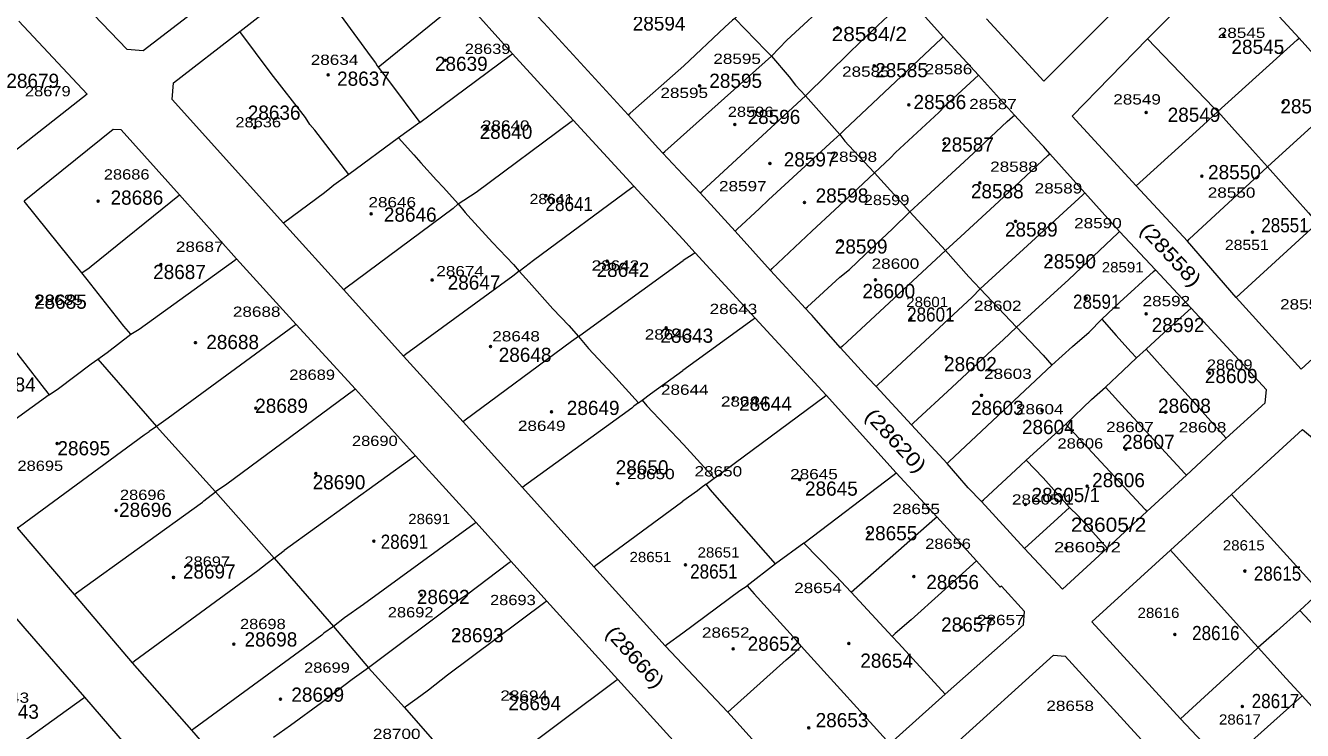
# Model space of a CAD drawing. Extents: x 650553 to 652508, y 239277 to 241647.
# Drawn here: x 651208.2 to 651532.3, y 240545.4 to 240724.2 of the extents above; entities that cross this region are included whole.
import ezdxf

# ---------------------------------------------------------------- set-up
doc = ezdxf.new("R2010")
doc.units = 0
doc.header["$PDMODE"] = 32
doc.header["$PDSIZE"] = 0.5
for name, color, linetype in [('19', 7, 'Continuous'), ('20', 7, 'Continuous'), ('6', 7, 'Continuous')]:
    doc.layers.add(name, color=color, linetype=linetype)
doc.layers.add('3', color=7, linetype='Continuous', lineweight=13)
doc.layers.add('5', color=7, linetype='Continuous', lineweight=13)

msp = doc.modelspace()

# ---------------------------------------------------------------- linework, layer by layer
at = {"layer": '3'}
for p, q in [((651450.066, 240711.621), (651459.242, 240701.47)), ((651375, 240686.46), (651369.97, 240691.81)), ((651498.782, 240591.135), (651514.288, 240605.241)), ((651461.794, 240591.569), (651450.843, 240603.463)), ((651427.585, 240542.041), (651441.626, 240554.652))]:
    msp.add_line(p, q, dxfattribs=at)
for points in [[(651262.55, 240722.73), (651280.74, 240736.96), (651297.28, 240750)], [(651302.75, 240750), (651319.13, 240731.15), (651331.81, 240717.05), (651347.16, 240700.26), (651362.6, 240683.5), (651375, 240670.03)], [(651369.97, 240691.81), (651368.88, 240693.01), (651361.16, 240701.58), (651339.76, 240724.88), (651328.09, 240737.32), (651316.83, 240750)], [(651255.48, 240731.26), (651238.03, 240717.81), (651233.93, 240718.13), (651208.28, 240744.9)], [(651492.971, 240720.815), (651513.155, 240740.984), (651531.466, 240721.038), (651544.042, 240707.095)], [(651450.066, 240711.621), (651441.147, 240721.392), (651432.124, 240731.442)], [(651452.07, 240725.954), (651466.7, 240710.154), (651486.051, 240729.467)], [(651206.48, 240725.3), (651223.8, 240706.84), (651205.18, 240692.18), (651190.09, 240680.31), (651175.31, 240668.77)], [(651273.67, 240674.07), (651245.34, 240705.49), (651245.71, 240709.71), (651262.55, 240722.73)], [(651490.103, 240683.542), (651473.849, 240701.275), (651492.971, 240720.815)], [(651459.242, 240701.47), (651466.169, 240693.962), (651466.625, 240693.468)], [(651247.26, 240681.25), (651232.45, 240697.8), (651230.43, 240697.87), (651207.83, 240679.65)], [(651468.174, 240691.712), (651467.071, 240692.962), (651466.625, 240693.468)], [(651504.03, 240652.528), (651494.997, 240662.26), (651485.912, 240672.017), (651477.107, 240681.763), (651468.174, 240691.712)], [(651375, 240686.46), (651379.385, 240681.794), (651388.317, 240672.1), (651397.237, 240662.126), (651406.195, 240652.406)], [(651515.523, 240655.238), (651503.098, 240669.537), (651490.103, 240683.542)], [(651375, 240540.13), (651358.51, 240558.37), (651340.48, 240578.22), (651331.44, 240588.29), (651322.55, 240598.18), (651307.18, 240615.11), (651291.88, 240631.98), (651276.83, 240648.43), (651261.75, 240665.07), (651247.26, 240681.25)], [(651386.452, 240550.075), (651370.54, 240566.91), (651352.46, 240586.94), (651334.34, 240607.07), (651319.27, 240623.71), (651304.14, 240640.39), (651288.94, 240657.22), (651273.67, 240674.07)], [(651375, 240670.03), (651378.161, 240666.59), (651393.367, 240650.006), (651411.384, 240630.427), (651429.147, 240610.758), (651439.535, 240599.585)], [(651552.783, 240656.051), (651531.957, 240637.06), (651515.523, 240655.238)], [(651406.195, 240652.406), (651407.346, 240651.167), (651407.834, 240650.642)], [(651415.077, 240642.469), (651408.255, 240650.167), (651407.834, 240650.642)], [(651512.913, 240619.579), (651522.834, 240628.544), (651523.235, 240631.812), (651504.03, 240652.528)], [(651424.073, 240632.686), (651422.042, 240634.784), (651415.077, 240642.469)], [(651450.843, 240603.463), (651447.471, 240606.976), (651444.838, 240609.985), (651442.127, 240613.146), (651433.055, 240622.967), (651424.073, 240632.686)], [(651295.65, 240493.45), (651290, 240500), (651285.79, 240504.89), (651259.52, 240534.92), (651250.39, 240545.47), (651235.33, 240562.59), (651220.57, 240579.93), (651206.08, 240596.78), (651191.08, 240613.86), (651178.77, 240628.25)], [(651514.288, 240605.241), (651532.372, 240621.712), (651558.3, 240600.133)], [(651273.44, 240495.96), (651269.97, 240500), (651254.58, 240517.89), (651246.43, 240527.23), (651238.05, 240536.69), (651223.17, 240553.84), (651208.09, 240571.29), (651193.7, 240587.9), (651178.92, 240605.09), (651167.95, 240618.06)], [(651482.725, 240591.652), (651492.847, 240600.974), (651502.894, 240610.13), (651512.913, 240619.579)], [(651439.535, 240599.585), (651442.973, 240595.755), (651446.245, 240592.076), (651449.555, 240588.435)], [(651558.3, 240600.133), (651576.968, 240584.586), (651595.445, 240569.14), (651576.219, 240550.158), (651565.481, 240539.702), (651554.984, 240529.272), (651535.929, 240510.959), (651512.56, 240536.549), (651501.394, 240548.39)], [(651461.794, 240591.569), (651471.364, 240581.255), (651482.725, 240591.652)], [(651441.626, 240554.652), (651461.507, 240572.227), (651461.755, 240575.583), (651455.903, 240582.029), (651455.612, 240581.723), (651449.555, 240588.435)], [(651501.394, 240548.39), (651478.878, 240572.937), (651498.782, 240591.135)], [(651443.339, 240541.167), (651469.158, 240564.482), (651472.119, 240564.219), (651489.626, 240545.044), (651506.288, 240526.995)], [(651386.452, 240550.075), (651408.664, 240525.362), (651427.585, 240542.041)]]:
    msp.add_lwpolyline(points, dxfattribs=at)
at = {"layer": '5'}
for p, q in [((651494.997, 240718.782), (651492.971, 240720.815)), ((651297.02, 240714.77), (651297.44, 240714.04)), ((651297.44, 240714.04), (651297.71, 240713.68)), ((651414.853, 240696.6), (651415.965, 240697.649)), ((651423.671, 240686.842), (651432.655, 240676.931)), ((651222.41, 240661.46), (651207.83, 240679.65)), ((651317.97, 240678.97), (651316.71, 240677.8)), ((651432.655, 240676.931), (651441.701, 240667.136)), ((651349.8, 240646.28), (651375.111, 240664.641)), ((651223.8, 240659.77), (651222.41, 240661.46)), ((651333.45, 240661.88), (651331.88, 240660.68)), ((651234.88, 240645.93), (651236.98, 240647.19)), ((651348.52, 240645.36), (651346.75, 240644.1)), ((651348.52, 240645.36), (651349.8, 240646.28)), ((651241.42, 240622.49), (651239.53, 240621.26)), ((651462.204, 240613.935), (651472.263, 240623.105)), ((651382.936, 240609.372), (651375.204, 240617.968)), ((651259.27, 240607.88), (651256.38, 240605.9)), ((651398.577, 240587.644), (651383.137, 240605.218)), ((651271.23, 240589.14), (651273.77, 240591.03)), ((651318.53, 240578.69), (651295.23, 240561.28)), ((651320.06, 240579.76), (651318.53, 240578.69)), ((651428.145, 240569.276), (651417.757, 240580.474)), ((651405.068, 240566.804), (651406.666, 240564.996)), ((651441.626, 240554.652), (651429.755, 240567.557)), ((651386.452, 240550.075), (651401.239, 240563.287)), ((651427.585, 240542.041), (651406.666, 240564.996))]:
    msp.add_line(p, q, dxfattribs=at)
for points in [[(651397.508, 240716.45), (651396.065, 240717.916), (651388.221, 240726.041), (651389.808, 240727.583), (651392.535, 240729.948), (651401.538, 240738.647), (651413.8, 240750)], [(651280.74, 240736.96), (651281.106, 240736.46), (651295.91, 240716.23), (651297.02, 240714.77)], [(651397.508, 240716.45), (651401.448, 240720.514), (651413.187, 240731.421), (651416.952, 240735.001)], [(651297.71, 240713.68), (651318.63, 240730.742), (651319.13, 240731.15)], [(651406.137, 240706.385), (651417.43, 240717.455), (651422.004, 240721.904), (651432.124, 240731.442)], [(651388.221, 240726.041), (651387.627, 240725.567), (651385.693, 240723.853), (651375.231, 240713.996)], [(651308.23, 240699.65), (651302.85, 240695.7), (651290.19, 240686.46), (651281.63, 240697.69), (651280.36, 240699.12), (651279.24, 240700.86), (651270.51, 240712.06), (651262.55, 240722.73)], [(651415.965, 240697.649), (651440.647, 240720.921), (651441.147, 240721.392)], [(651510.816, 240702.43), (651530.966, 240720.587), (651531.466, 240721.038)], [(651494.997, 240718.782), (651509.769, 240703.453), (651510.816, 240702.43), (651507.101, 240698.952), (651490.103, 240683.542)], [(651308.23, 240699.65), (651331.31, 240716.681), (651331.81, 240717.05)], [(651369.97, 240691.81), (651370.47, 240692.257), (651397.508, 240716.45)], [(651397.508, 240716.45), (651402.046, 240711.216), (651403.645, 240709.141), (651406.137, 240706.385)], [(651297.71, 240713.68), (651300.57, 240709.91), (651308.23, 240699.65)], [(651361.16, 240701.58), (651361.66, 240702.034), (651375.231, 240713.996)], [(651397.237, 240662.126), (651397.737, 240662.598), (651407.788, 240672.086), (651419.413, 240682.852), (651423.671, 240686.842), (651427.727, 240690.639), (651429.015, 240692.032), (651439.996, 240702.134), (651441.65, 240703.884), (651450.066, 240711.621)], [(651379.385, 240681.794), (651379.885, 240682.254), (651406.137, 240706.385), (651414.853, 240696.6)], [(651503.098, 240669.537), (651503.598, 240670.001), (651523.455, 240688.424), (651544.042, 240707.095)], [(651510.816, 240702.43), (651514.382, 240698.422), (651519.659, 240692.646), (651523.455, 240688.424), (651533.859, 240676.692), (651536.108, 240674.074), (651534.428, 240672.54), (651515.523, 240655.238)], [(651322.57, 240681.97), (651346.66, 240699.888), (651347.16, 240700.26)], [(651406.195, 240652.406), (651406.695, 240652.866), (651414.889, 240660.398), (651417.291, 240662.305), (651421.347, 240666.179), (651428.271, 240672.687), (651432.655, 240676.931), (651435.738, 240679.885), (651447.579, 240690.627), (651457.358, 240699.896)], [(651457.358, 240699.896), (651458.742, 240701.052), (651459.242, 240701.47)], [(651302.85, 240695.7), (651306.71, 240691.41), (651308.51, 240689.4), (651312.47, 240685.01), (651314.24, 240683.17), (651317.97, 240678.97), (651322.57, 240681.97)], [(651388.317, 240672.1), (651388.817, 240672.561), (651394.509, 240677.803), (651396.795, 240680.027), (651413.337, 240695.27), (651414.853, 240696.6), (651416.133, 240694.931), (651417.168, 240693.831), (651423.671, 240686.842)], [(651455.223, 240679.578), (651467.674, 240691.244), (651468.174, 240691.712)], [(651290.19, 240686.46), (651286.44, 240683.73), (651285.4, 240682.9), (651284.08, 240681.82), (651273.67, 240674.07)], [(651337.07, 240664.68), (651362.1, 240683.131), (651362.6, 240683.5)], [(651222.41, 240661.46), (651224.3, 240662.79), (651224.84, 240663.17), (651247.26, 240681.25)], [(651317.97, 240678.97), (651319.76, 240676.79), (651320.41, 240676.07), (651326.72, 240669.19), (651332.06, 240663.57), (651333.45, 240661.88), (651334.89, 240663.04), (651337.07, 240664.68)], [(651450.532, 240657.402), (651447.632, 240660.461), (651441.701, 240667.136), (651445.568, 240670.742), (651455.223, 240679.578)], [(651450.532, 240657.402), (651476.607, 240681.305), (651477.107, 240681.763)], [(651316.71, 240677.8), (651289.44, 240657.591), (651288.94, 240657.22)], [(651479.292, 240665.702), (651485.412, 240671.54), (651485.912, 240672.017)], [(651378.161, 240666.59), (651377.661, 240666.27), (651375.111, 240664.641)], [(651441.701, 240667.136), (651415.577, 240642.932), (651415.077, 240642.469)], [(651236.98, 240647.19), (651261.25, 240664.709), (651261.75, 240665.07)], [(651433.055, 240622.967), (651433.555, 240623.428), (651443.291, 240632.404), (651453.665, 240642.07), (651456.331, 240644.526), (651459.756, 240647.697), (651472.974, 240659.832), (651479.292, 240665.702)], [(651214.11, 240630.58), (651216.51, 240632.17), (651224.8, 240638.43), (651226.52, 240639.61), (651228.85, 240641.3), (651234.88, 240645.93), (651233.08, 240647.97), (651223.8, 240659.77)], [(651331.88, 240660.68), (651304.64, 240640.756), (651304.14, 240640.39)], [(651333.45, 240661.88), (651336.03, 240659.12), (651342.05, 240652.38), (651346.09, 240648.16), (651348.52, 240645.36)], [(651485.974, 240654.012), (651494.497, 240661.803), (651494.997, 240662.26)], [(651424.073, 240632.686), (651424.573, 240633.149), (651448.486, 240655.307), (651450.532, 240657.402), (651459.756, 240647.697)], [(651468.725, 240638.079), (651473.932, 240642.785), (651478.179, 240646.482), (651481.425, 240649.754), (651485.974, 240654.012)], [(651393.367, 240650.006), (651392.867, 240649.636), (651375, 240636.7)], [(651481.425, 240649.754), (651485.043, 240645.594), (651488.736, 240641.473), (651490.18, 240639.906)], [(651482.333, 240632.528), (651486.768, 240636.696), (651490.18, 240639.906), (651492.619, 240642.118), (651497.168, 240646.274), (651504.03, 240652.528)], [(651276.83, 240648.43), (651276.33, 240648.064), (651244.33, 240624.61), (651241.42, 240622.49)], [(651459.756, 240647.697), (651466.514, 240640.62), (651468.725, 240638.079)], [(651201.87, 240646.38), (651212.9, 240632.13), (651214.11, 240630.58)], [(651346.75, 240644.1), (651319.77, 240624.081), (651319.27, 240623.71)], [(651348.52, 240645.36), (651351.1, 240642.31), (651357.14, 240635.83), (651363.78, 240628.54), (651364.71, 240629.23), (651366.83, 240630.77), (651375, 240636.7)], [(651492.619, 240642.118), (651495.456, 240638.996), (651497.692, 240636.506), (651504.095, 240629.427), (651505.233, 240628.074), (651512.913, 240619.579)], [(651226.52, 240639.61), (651241.42, 240622.49), (651256.38, 240605.9), (651271.23, 240589.14), (651286.36, 240571.79), (651295.23, 240561.28), (651304.36, 240551.2), (651321.96, 240531.12)], [(651468.725, 240638.079), (651442.627, 240613.615), (651442.127, 240613.146)], [(651214.11, 240630.58), (651191.58, 240614.223), (651191.08, 240613.86)], [(651291.88, 240631.98), (651291.38, 240631.61), (651259.27, 240607.88)], [(651383.847, 240610.025), (651410.884, 240630.057), (651411.384, 240630.427)], [(651472.263, 240623.105), (651478.769, 240629.331), (651482.333, 240632.528), (651487.355, 240627.03), (651492.646, 240621.279)], [(651362.07, 240627.2), (651334.84, 240607.433), (651334.34, 240607.07)], [(651363.78, 240628.54), (651362.6, 240627.68), (651362.07, 240627.2)], [(651364.71, 240629.23), (651365.89, 240627.74), (651375.204, 240617.968)], [(651206.08, 240596.78), (651206.58, 240597.147), (651238.25, 240620.37), (651239.53, 240621.26)], [(651472.263, 240623.105), (651492.382, 240601.474), (651492.847, 240600.974)], [(651492.646, 240621.279), (651502.434, 240610.63), (651502.894, 240610.13)], [(651307.18, 240615.11), (651306.68, 240614.75), (651273.77, 240591.03)], [(651405.736, 240592.946), (651428.647, 240610.378), (651429.147, 240610.758)], [(651450.843, 240603.463), (651451.343, 240603.926), (651460.712, 240612.605), (651462.204, 240613.935), (651466.47, 240609.525), (651473.167, 240601.991)], [(651383.137, 240605.218), (651382.05, 240606.444), (651380.95, 240607.899), (651379.685, 240606.913), (651378.724, 240606.209), (651375, 240603.58)], [(651380.95, 240607.899), (651382.936, 240609.372), (651383.847, 240610.025)], [(651220.57, 240579.93), (651221.07, 240580.29), (651253.04, 240603.3), (651253.45, 240603.67), (651256.38, 240605.9)], [(651514.288, 240605.241), (651534.939, 240582.5), (651536.83, 240580.491)], [(651352.46, 240586.94), (651352.96, 240587.309), (651374.66, 240603.33), (651375, 240603.58)], [(651482.725, 240591.652), (651475.351, 240599.843), (651473.167, 240601.991), (651470.223, 240599.254), (651461.794, 240591.569)], [(651322.55, 240598.18), (651322.05, 240597.816), (651293.95, 240577.34)], [(651417.757, 240580.474), (651439.035, 240599.146), (651439.535, 240599.585)], [(651417.757, 240580.474), (651413.873, 240584.632), (651409.479, 240589.118), (651405.736, 240592.946), (651398.577, 240587.644), (651391.355, 240582.088)], [(651271.23, 240589.14), (651269.49, 240587.76), (651267.11, 240585.89)], [(651331.44, 240588.29), (651330.94, 240587.915), (651320.06, 240579.76)], [(651449.555, 240588.435), (651440.708, 240580.442), (651432.961, 240573.459), (651428.954, 240570.03), (651428.145, 240569.276), (651429.755, 240567.557)], [(651498.782, 240591.135), (651519.318, 240568.419), (651521.12, 240566.46)], [(651267.11, 240585.89), (651235.83, 240562.957), (651235.33, 240562.59)], [(651558.897, 240568.089), (651556.316, 240570.781), (651547.771, 240579.423), (651542.01, 240585.362), (651536.83, 240580.491), (651536.235, 240580.068), (651535.098, 240579.019), (651531.648, 240575.861)], [(651375, 240570.19), (651389.495, 240580.882), (651391.355, 240582.088), (651393.158, 240580.039), (651403.892, 240568.259)], [(651293.95, 240577.34), (651289.14, 240573.98), (651286.36, 240571.79), (651283.9, 240570.08), (651283.37, 240569.6)], [(651340.48, 240578.22), (651339.98, 240577.847), (651315.29, 240559.41)], [(651565.481, 240539.702), (651565.011, 240540.202), (651555.234, 240550.609), (651531.648, 240575.861), (651525.86, 240570.63), (651521.12, 240566.46), (651519.553, 240565.053), (651501.394, 240548.39)], [(651283.37, 240569.6), (651250.89, 240545.836), (651250.39, 240545.47)], [(651370.54, 240566.91), (651371.04, 240567.278), (651375, 240570.19)], [(651401.239, 240563.287), (651403.338, 240565.117), (651405.068, 240566.804), (651403.892, 240568.259)], [(651532.289, 240554.148), (651528.2, 240558.584), (651525.031, 240562.086), (651521.12, 240566.46)], [(651295.23, 240561.28), (651292.83, 240559.62), (651291.06, 240558.34), (651283.32, 240552.39), (651275.38, 240546.66), (651271.14, 240543.62)], [(651315.29, 240559.41), (651310.44, 240555.59), (651308.54, 240554.21)], [(651358.51, 240558.37), (651358.01, 240557.996), (651330.75, 240537.61)], [(651192.28, 240531.72), (651222.67, 240553.482), (651223.17, 240553.84)], [(651308.54, 240554.21), (651304.86, 240551.56), (651304.36, 240551.2)], [(651512.56, 240536.549), (651513.06, 240536.995), (651532.289, 240554.148)], [(651532.289, 240554.148), (651554.528, 240529.772), (651554.984, 240529.272)]]:
    msp.add_lwpolyline(points, dxfattribs=at)
at = {"layer": '6'}
for p in [(651414.316, 240723.628), (651512.358, 240721.707), (651314.696, 240715.4), (651284.994, 240711.71), (651423.628, 240714.021), (651379.288, 240708.925), (651527.402, 240704.731), (651432.364, 240704.117), (651492.64, 240702.178), (651266.366, 240698.4), (651388.189, 240699.122), (651325.066, 240698.01), (651441.442, 240694.276), (651397.141, 240689.242), (651506.81, 240685.983), (651450.437, 240684.303), (651226.572, 240679.665), (651340.247, 240681.07), (651405.879, 240679.363), (651295.891, 240676.46), (651459.491, 240674.557), (651415.096, 240669.624), (651519.612, 240671.831), (651242.53, 240663.59), (651355.779, 240664.43), (651468.386, 240664.73), (651311.386, 240659.68), (651423.902, 240659.7), (651211.216, 240655.115), (651477.435, 240655.048), (651432.886, 240649.911), (651492.645, 240651.083), (651370.789, 240647.565), (651251.282, 240643.78), (651326.209, 240642.795), (651441.903, 240640.184), (651508.703, 240636.053), (651450.848, 240630.421), (651266.591, 240627.165), (651387.865, 240629.689), (651341.68, 240626.215), (651466.206, 240626.608), (651497.592, 240626.124), (651216.167, 240618.195), (651487.49, 240616.751), (651281.882, 240610.56), (651358.469, 240608.085), (651404.682, 240609.035), (651477.635, 240607.378), (651231.129, 240601.21), (651461.994, 240602.752), (651422.129, 240595.616), (651296.593, 240593.45), (651472.273, 240591.623), (651375.677, 240587.404), (651517.728, 240585.85), (651245.716, 240584.245), (651433.694, 240584.43), (651308.623, 240579.73), (651317.844, 240569.745), (651445.728, 240571.543), (651499.947, 240569.762), (651260.997, 240567.305), (651387.825, 240566.081), (651417.162, 240567.493), (651272.871, 240553.355), (651331.368, 240554.67), (651517.056, 240551.504), (651406.971, 240546.083)]:
    msp.add_point(p, dxfattribs=at)

# ---------------------------------------------------------------- texts
at = {"layer": '19'}
for s, p in [('28594', (651362.297, 240722.96)), ('28545', (651514.298, 240717.034)), ('28639', (651312.081, 240712.723)), ('28585', (651423.855, 240711.107)), ('28679', (651203.28, 240708.413)), ('28637', (651287.243, 240708.951)), ('28595', (651381.737, 240708.412)), ('28586', (651433.574, 240703.023)), ('28546', (651526.719, 240701.947)), ('28636', (651264.565, 240700.33)), ('28596', (651391.456, 240699.252)), ('28549', (651498.101, 240699.792)), ('28640', (651323.42, 240695.48)), ('28587', (651440.594, 240692.248)), ('28597', (651400.636, 240688.476)), ('28550', (651508.359, 240685.243)), ('28686', (651229.739, 240678.777)), ('28598', (651408.735, 240679.315)), ('28588', (651448.152, 240680.393)), ('28646', (651299.123, 240674.466)), ('28589', (651456.792, 240670.695)), ('28599', (651413.595, 240666.384)), ('28590', (651466.512, 240662.611)), ('28687', (651240.538, 240659.918)), ('28642', (651353.119, 240660.456)), ('28647', (651315.322, 240657.223)), ('28600', (651420.613, 240655.068)), ('28685', (651210.3, 240652.375)), ('28592', (651494.05, 240646.448)), ('28643', (651369.318, 240643.753)), ('28688', (651254.037, 240642.137)), ('28648', (651328.28, 240638.903)), ('28602', (651441.33, 240636.539)), ('28609', (651507.549, 240633.514)), ('28684', (651197.34, 240631.361)), ('28689', (651266.456, 240625.972)), ('28649', (651345.56, 240625.433)), ('28644', (651389.295, 240626.51)), ('28603', (651448.153, 240625.433)), ('28608', (651495.669, 240625.971)), ('28604', (651461.111, 240620.583)), ('28695', (651216.24, 240615.196)), ('28607', (651486.491, 240616.811)), ('28650', (651357.978, 240610.346)), ('28606', (651478.931, 240607.112)), ('28690', (651281.035, 240606.575)), ('28645', (651406.035, 240604.957)), ('28605/1', (651463.542, 240603.34)), ('28696', (651231.899, 240599.57)), ('28655', (651421.156, 240593.642)), ('28697', (651248.098, 240583.944)), ('28656', (651436.814, 240581.249)), ('28692', (651307.494, 240577.478)), ('28657', (651440.593, 240570.472)), ('28698', (651263.757, 240566.701)), ('28693', (651316.133, 240567.779)), ('28652', (651391.457, 240565.623)), ('28654', (651420.074, 240561.312)), ('28699', (651275.636, 240552.692)), ('28694', (651330.712, 240550.537)), ('28743', (651198.15, 240548.381)), ('28653', (651408.736, 240546.225))]:
    msp.add_text(s, height=3.6, dxfattribs=at).set_placement(p)
for s, width, p in [('28584/2', 1.1, (651412.785, 240720.265)), ('28641', 0.9, (651340.16, 240677.16)), ('28551', 0.9, (651521.859, 240671.773)), ('28591', 0.9, (651474.071, 240652.374)), ('28601', 0.9, (651431.954, 240649.141)), ('28605/2', 1.1, (651473.525, 240595.796)), ('28691', 0.9, (651298.314, 240591.487)), ('28651', 0.9, (651376.878, 240583.943)), ('28615', 0.9, (651519.968, 240583.403)), ('28616', 0.9, (651504.309, 240568.316)), ('28617', 0.9, (651519.428, 240551.073))]:
    msp.add_text(s, height=3.6, dxfattribs=dict(at, width=width)).set_placement(p)
for s, rotation, width, p in [('(28558)', 312.957, 1.2, (651490.763, 240672.19)), ('(28620)', 312.957, 1.2, (651420.981, 240625.008)), ('(28666)', 312.249, 1.15, (651355.148, 240569.895))]:
    msp.add_text(s, height=3.6, rotation=rotation, dxfattribs=dict(at, width=width)).set_placement(p)
at = {"layer": '20'}
for s, width, p in [('28545', 1.25, (651510.819, 240721.076)), ('28639', 1.2, (651319.657, 240717.012)), ('28634', 1.25, (651280.551, 240714.242)), ('28595', 1.25, (651382.757, 240714.488)), ('28586', 1.25, (651436.422, 240711.856)), ('28585', 1.25, (651415.443, 240711.239)), ('28679', 1.2, (651208.003, 240706.272)), ('28595', 1.25, (651369.328, 240705.845)), ('28587', 1.25, (651447.709, 240703.022)), ('28549', 1.25, (651484.296, 240704.198)), ('28596', 1.2, (651386.43, 240701.054)), ('28636', 1.2, (651261.425, 240698.396)), ('28640', 1.25, (651324.008, 240697.567)), ('28598', 1.25, (651412.253, 240689.644)), ('28588', 1.25, (651453.04, 240687.121)), ('28686', 1.2, (651228.027, 240685.17)), ('28597', 1.25, (651384.194, 240682.177)), ('28589', 1.25, (651464.33, 240681.628)), ('28550', 1.25, (651508.284, 240680.55)), ('28646', 1.25, (651295.201, 240678.106)), ('28641', 1.15, (651336.111, 240678.929)), ('28599', 1.2, (651420.942, 240678.675)), ('28590', 1.25, (651474.356, 240672.794)), ('28687', 1.25, (651246.319, 240666.822)), ('28551', 1.15, (651512.636, 240667.289)), ('28674', 1.25, (651312.431, 240660.632)), ('28642', 1.25, (651351.858, 240662.069)), ('28600', 1.25, (651422.949, 240662.523)), ('28591', 1.1, (651481.368, 240661.605)), ('28685', 1.25, (651210.599, 240653.346)), ('28688', 1.25, (651260.787, 240650.338)), ('28643', 1.25, (651381.823, 240651.036)), ('28601', 1.1, (651431.728, 240652.806)), ('28602', 1.25, (651448.912, 240651.849)), ('28592', 1.25, (651491.732, 240653.033)), ('28552', 1.25, (651526.637, 240652.209)), ('28648', 1.25, (651326.641, 240644.1)), ('28643', 1.25, (651365.347, 240644.577)), ('28689', 1.2, (651275.111, 240634.348)), ('28603', 1.25, (651451.497, 240634.588)), ('28609', 1.2, (651508.057, 240636.911)), ('28644', 1.25, (651369.466, 240630.547)), ('28644', 1.25, (651384.691, 240627.566)), ('28604', 1.25, (651459.581, 240625.608)), ('28649', 1.25, (651333.149, 240621.388)), ('28607', 1.25, (651482.473, 240621.084)), ('28608', 1.25, (651500.914, 240621.011)), ('28690', 1.2, (651291.026, 240617.571)), ('28606', 1.2, (651470.14, 240616.921)), ('28695', 1.2, (651206.102, 240611.255)), ('28650', 1.25, (651360.852, 240609.159)), ('28650', 1.25, (651377.991, 240609.848)), ('28645', 1.25, (651402.273, 240609.129)), ('28696', 1.2, (651232.116, 240603.879)), ('28605/1', 1.25, (651458.575, 240602.714)), ('28655', 1.25, (651428.207, 240600.299)), ('28691', 1.1, (651305.301, 240597.746)), ('28651', 1.1, (651378.757, 240589.268)), ('28656', 1.2, (651436.554, 240591.473)), ('28605/2', 1.35, (651469.261, 240590.594)), ('28615', 1.1, (651512.101, 240591.068)), ('28697', 1.2, (651248.479, 240586.956)), ('28651', 1.1, (651361.477, 240588.1)), ('28654', 1.25, (651403.287, 240580.252)), ('28693', 1.2, (651326.073, 240577.198)), ('28692', 1.2, (651300.119, 240574.083)), ('28616', 1.1, (651490.457, 240573.935)), ('28698', 1.2, (651262.595, 240571.113)), ('28657', 1.25, (651449.691, 240572.135)), ('28652', 1.25, (651379.868, 240568.935)), ('28699', 1.2, (651278.867, 240560.05)), ('28743', 1.25, (651196.97, 240552.422)), ('28694', 1.25, (651328.694, 240552.949)), ('28658', 1.25, (651467.308, 240550.362)), ('28617', 1.1, (651511.127, 240546.893)), ('28700', 1.25, (651296.335, 240543.243))]:
    msp.add_text(s, height=2.6, dxfattribs=dict(at, width=width)).set_placement(p)

doc.saveas('drawing.dxf')
